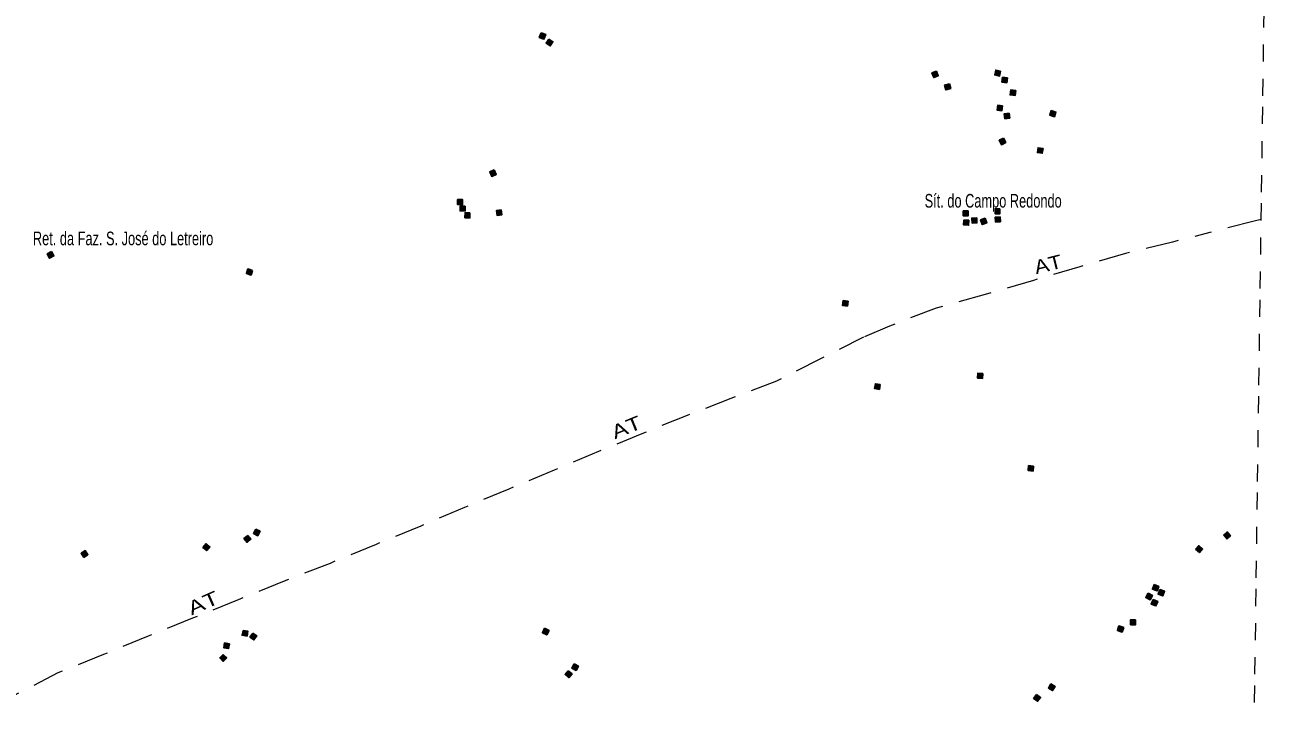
# Model space of a CAD drawing. Extents: x 679 to 705, y 7427.4 to 7455.4.
# Drawn here: x 697.64 to 704.9, y 7443.57 to 7447.55 of the extents above; entities that cross this region are included whole.
import ezdxf
from ezdxf.enums import TextEntityAlignment as Align

# ---------------------------------------------------------------- set-up
doc = ezdxf.new("R2010")
doc.units = 0
doc.header["$LTSCALE"] = 0.032
doc.linetypes.add('DOT_DASHED', pattern=[7.7, 5, -1.2, 0.3, -1.2])
doc.linetypes.add('SHORT_DASHED', pattern=[2.7, 1.5, -1.2])
for name, color, linetype, lineweight in [('2', 7, 'Continuous', 25), ('56', 7, 'DOT_DASHED', 13), ('58', 7, 'SHORT_DASHED', 13)]:
    doc.layers.add(name, color=color, linetype=linetype, lineweight=lineweight)
doc.layers.add('61', color=7, linetype='Continuous')

msp = doc.modelspace()

# ---------------------------------------------------------------- hatches: boundary and pattern name
at = {"layer": '2'}
for points in [[(700.6624, 7447.5073), (700.6893, 7447.4964), (700.6784, 7447.4695), (700.6515, 7447.4804)], [(700.7072, 7447.4701), (700.7317, 7447.4546), (700.7161, 7447.4301), (700.6917, 7447.4456)], [(702.9796, 7447.2825), (702.9902, 7447.2555), (702.9632, 7447.2449), (702.9526, 7447.2719)], [(703.3556, 7447.2814), (703.3489, 7447.2532), (703.3207, 7447.2599), (703.3273, 7447.2881)], [(703.0551, 7447.2082), (703.0629, 7447.1803), (703.035, 7447.1725), (703.0272, 7447.2004)], [(703.3959, 7447.2431), (703.3921, 7447.2144), (703.3633, 7447.2181), (703.3671, 7447.2469)], [(703.4438, 7447.168), (703.4398, 7447.1393), (703.4111, 7447.1433), (703.4151, 7447.172)], [(703.3672, 7447.0788), (703.3634, 7447.05), (703.3346, 7447.0538), (703.3385, 7447.0826)], [(703.4048, 7447.0362), (703.4089, 7447.0075), (703.3802, 7447.0034), (703.3761, 7447.0321)], [(703.6526, 7447.0522), (703.68, 7447.0427), (703.6705, 7447.0153), (703.6431, 7447.0248)], [(703.3723, 7446.8905), (703.3859, 7446.8649), (703.3602, 7446.8513), (703.3467, 7446.877)], [(703.604, 7446.8293), (703.5995, 7446.8007), (703.5709, 7446.8052), (703.5753, 7446.8338)], [(700.3873, 7446.7035), (700.3994, 7446.6772), (700.3731, 7446.6651), (700.361, 7446.6914)], [(700.1727, 7446.5295), (700.2017, 7446.5295), (700.2017, 7446.5005), (700.1727, 7446.5005)], [(700.2179, 7446.4912), (700.2167, 7446.4622), (700.1878, 7446.4634), (700.1889, 7446.4924)], [(700.4288, 7446.4697), (700.4331, 7446.441), (700.4044, 7446.4367), (700.4002, 7446.4654)], [(703.1651, 7446.463), (703.1651, 7446.434), (703.1361, 7446.434), (703.1361, 7446.463)], [(703.3517, 7446.4758), (703.3517, 7446.4468), (703.3227, 7446.4468), (703.3227, 7446.4758)], [(700.2454, 7446.4516), (700.2447, 7446.4226), (700.2158, 7446.4232), (700.2164, 7446.4522)], [(703.1691, 7446.408), (703.1674, 7446.3791), (703.1385, 7446.3807), (703.1401, 7446.4096)], [(703.2153, 7446.4223), (703.2169, 7446.3933), (703.188, 7446.3917), (703.1864, 7446.4207)], [(703.2649, 7446.4205), (703.2746, 7446.3931), (703.2473, 7446.3835), (703.2376, 7446.4108)], [(703.3527, 7446.4285), (703.3539, 7446.3995), (703.3249, 7446.3983), (703.3237, 7446.4273)], [(697.7938, 7446.2253), (697.8075, 7446.1997), (697.782, 7446.186), (697.7683, 7446.2115)], [(698.9716, 7446.1148), (698.9629, 7446.0872), (698.9352, 7446.0959), (698.944, 7446.1236)], [(702.4614, 7445.9341), (702.4574, 7445.9054), (702.4287, 7445.9093), (702.4326, 7445.9381)], [(703.2515, 7445.5106), (703.2493, 7445.4817), (703.2204, 7445.4839), (703.2226, 7445.5128)], [(702.6498, 7445.4455), (702.6451, 7445.4169), (702.6165, 7445.4216), (702.6212, 7445.4502)], [(703.5486, 7444.9677), (703.5458, 7444.9388), (703.517, 7444.9416), (703.5198, 7444.9705)], [(698.9895, 7444.5986), (699.0153, 7444.5853), (699.0021, 7444.5595), (698.9763, 7444.5728)], [(704.6618, 7444.5626), (704.6837, 7444.5815), (704.7027, 7444.5596), (704.6807, 7444.5406)], [(698.6984, 7444.5133), (698.721, 7444.4951), (698.7028, 7444.4725), (698.6802, 7444.4907)], [(698.9428, 7444.5613), (698.9616, 7444.5392), (698.9395, 7444.5204), (698.9207, 7444.5424)], [(704.4985, 7444.4799), (704.5175, 7444.5017), (704.5394, 7444.4827), (704.5203, 7444.4608)], [(697.9815, 7444.4321), (697.9658, 7444.4565), (697.9902, 7444.4722), (698.0059, 7444.4478)], [(704.2194, 7444.223), (704.245, 7444.2093), (704.2313, 7444.1837), (704.2057, 7444.1974)], [(704.2553, 7444.2731), (704.2825, 7444.2629), (704.2722, 7444.2357), (704.2451, 7444.246)], [(704.289, 7444.2445), (704.316, 7444.2339), (704.3055, 7444.2069), (704.2785, 7444.2175)], [(704.2491, 7444.1854), (704.2761, 7444.175), (704.2657, 7444.1479), (704.2386, 7444.1584)], [(704.1463, 7444.0669), (704.1463, 7444.0379), (704.1173, 7444.0379), (704.1173, 7444.0669)], [(698.9157, 7444.005), (698.9441, 7443.9996), (698.9387, 7443.9711), (698.9102, 7443.9765)], [(698.9726, 7443.989), (698.9963, 7443.9723), (698.9796, 7443.9486), (698.9559, 7443.9653)], [(700.683, 7444.0171), (700.7089, 7444.0039), (700.6957, 7443.978), (700.6699, 7443.9912)], [(704.0767, 7444.022), (704.0675, 7443.9945), (704.04, 7444.0036), (704.0491, 7444.0312)], [(698.836, 7443.9261), (698.8304, 7443.8977), (698.8019, 7443.9034), (698.8076, 7443.9318)], [(698.7988, 7443.8643), (698.8196, 7443.844), (698.7993, 7443.8233), (698.7786, 7443.8436)], [(700.8216, 7443.7685), (700.8435, 7443.7495), (700.8244, 7443.7276), (700.8026, 7443.7467)], [(700.8554, 7443.8091), (700.8811, 7443.7957), (700.8677, 7443.77), (700.842, 7443.7834)], [(703.566, 7443.6297), (703.5892, 7443.6123), (703.5718, 7443.5891), (703.5486, 7443.6065)], [(703.6507, 7443.6916), (703.6751, 7443.6761), (703.6596, 7443.6516), (703.6351, 7443.6671)]]:
    msp.add_hatch(color=256, dxfattribs=at).paths.add_polyline_path(points)

# ---------------------------------------------------------------- linework, layer by layer
for points in [[(700.6624, 7447.5073), (700.6893, 7447.4964), (700.6784, 7447.4695), (700.6515, 7447.4804)], [(700.7072, 7447.4701), (700.7317, 7447.4546), (700.7161, 7447.4301), (700.6917, 7447.4456)], [(702.9796, 7447.2825), (702.9902, 7447.2555), (702.9632, 7447.2449), (702.9526, 7447.2719)], [(703.3556, 7447.2814), (703.3489, 7447.2532), (703.3207, 7447.2599), (703.3273, 7447.2881)], [(703.0551, 7447.2082), (703.0629, 7447.1803), (703.035, 7447.1725), (703.0272, 7447.2004)], [(703.3959, 7447.2431), (703.3921, 7447.2144), (703.3633, 7447.2181), (703.3671, 7447.2469)], [(703.4438, 7447.168), (703.4398, 7447.1393), (703.4111, 7447.1433), (703.4151, 7447.172)], [(703.3672, 7447.0788), (703.3634, 7447.05), (703.3346, 7447.0538), (703.3385, 7447.0826)], [(703.4048, 7447.0362), (703.4089, 7447.0075), (703.3802, 7447.0034), (703.3761, 7447.0321)], [(703.6526, 7447.0522), (703.68, 7447.0427), (703.6705, 7447.0153), (703.6431, 7447.0248)], [(703.3723, 7446.8905), (703.3859, 7446.8649), (703.3602, 7446.8513), (703.3467, 7446.877)], [(703.604, 7446.8293), (703.5995, 7446.8007), (703.5709, 7446.8052), (703.5753, 7446.8338)], [(700.3873, 7446.7035), (700.3994, 7446.6772), (700.3731, 7446.6651), (700.361, 7446.6914)], [(700.1727, 7446.5295), (700.2017, 7446.5295), (700.2017, 7446.5005), (700.1727, 7446.5005)], [(700.2179, 7446.4912), (700.2167, 7446.4622), (700.1878, 7446.4634), (700.1889, 7446.4924)], [(700.4288, 7446.4697), (700.4331, 7446.441), (700.4044, 7446.4367), (700.4002, 7446.4654)], [(703.1651, 7446.463), (703.1651, 7446.434), (703.1361, 7446.434), (703.1361, 7446.463)], [(703.3517, 7446.4758), (703.3517, 7446.4468), (703.3227, 7446.4468), (703.3227, 7446.4758)], [(700.2454, 7446.4516), (700.2447, 7446.4226), (700.2158, 7446.4232), (700.2164, 7446.4522)], [(703.1691, 7446.408), (703.1674, 7446.3791), (703.1385, 7446.3807), (703.1401, 7446.4096)], [(703.2153, 7446.4223), (703.2169, 7446.3933), (703.188, 7446.3917), (703.1864, 7446.4207)], [(703.2649, 7446.4205), (703.2746, 7446.3931), (703.2473, 7446.3835), (703.2376, 7446.4108)], [(703.3527, 7446.4285), (703.3539, 7446.3995), (703.3249, 7446.3983), (703.3237, 7446.4273)], [(697.7938, 7446.2253), (697.8075, 7446.1997), (697.782, 7446.186), (697.7683, 7446.2115)], [(698.9716, 7446.1148), (698.9629, 7446.0872), (698.9352, 7446.0959), (698.944, 7446.1236)], [(702.4614, 7445.9341), (702.4574, 7445.9054), (702.4287, 7445.9093), (702.4326, 7445.9381)], [(703.2515, 7445.5106), (703.2493, 7445.4817), (703.2204, 7445.4839), (703.2226, 7445.5128)], [(702.6498, 7445.4455), (702.6451, 7445.4169), (702.6165, 7445.4216), (702.6212, 7445.4502)], [(703.5486, 7444.9677), (703.5458, 7444.9388), (703.517, 7444.9416), (703.5198, 7444.9705)], [(698.9895, 7444.5986), (699.0153, 7444.5853), (699.0021, 7444.5595), (698.9763, 7444.5728)], [(704.6618, 7444.5626), (704.6837, 7444.5815), (704.7027, 7444.5596), (704.6807, 7444.5406)], [(698.6984, 7444.5133), (698.721, 7444.4951), (698.7028, 7444.4725), (698.6802, 7444.4907)], [(698.9428, 7444.5613), (698.9616, 7444.5392), (698.9395, 7444.5204), (698.9207, 7444.5424)], [(704.4985, 7444.4799), (704.5175, 7444.5017), (704.5394, 7444.4827), (704.5203, 7444.4608)], [(697.9815, 7444.4321), (697.9658, 7444.4565), (697.9902, 7444.4722), (698.0059, 7444.4478)], [(704.2194, 7444.223), (704.245, 7444.2093), (704.2313, 7444.1837), (704.2057, 7444.1974)], [(704.2553, 7444.2731), (704.2825, 7444.2629), (704.2722, 7444.2357), (704.2451, 7444.246)], [(704.289, 7444.2445), (704.316, 7444.2339), (704.3055, 7444.2069), (704.2785, 7444.2175)], [(704.2491, 7444.1854), (704.2761, 7444.175), (704.2657, 7444.1479), (704.2386, 7444.1584)], [(704.1463, 7444.0669), (704.1463, 7444.0379), (704.1173, 7444.0379), (704.1173, 7444.0669)], [(698.9157, 7444.005), (698.9441, 7443.9996), (698.9387, 7443.9711), (698.9102, 7443.9765)], [(698.9726, 7443.989), (698.9963, 7443.9723), (698.9796, 7443.9486), (698.9559, 7443.9653)], [(700.683, 7444.0171), (700.7089, 7444.0039), (700.6957, 7443.978), (700.6699, 7443.9912)], [(704.0767, 7444.022), (704.0675, 7443.9945), (704.04, 7444.0036), (704.0491, 7444.0312)], [(698.836, 7443.9261), (698.8304, 7443.8977), (698.8019, 7443.9034), (698.8076, 7443.9318)], [(698.7988, 7443.8643), (698.8196, 7443.844), (698.7993, 7443.8233), (698.7786, 7443.8436)], [(700.8216, 7443.7685), (700.8435, 7443.7495), (700.8244, 7443.7276), (700.8026, 7443.7467)], [(700.8554, 7443.8091), (700.8811, 7443.7957), (700.8677, 7443.77), (700.842, 7443.7834)], [(703.566, 7443.6297), (703.5892, 7443.6123), (703.5718, 7443.5891), (703.5486, 7443.6065)], [(703.6507, 7443.6916), (703.6751, 7443.6761), (703.6596, 7443.6516), (703.6351, 7443.6671)]]:
    msp.add_lwpolyline(points, close=True, dxfattribs=at)
at = {"layer": '56'}
msp.add_lwpolyline([(704.8826, 7446.4125), (704.842, 7446.4026), (704.3631, 7446.2806), (704.0865, 7446.213), (703.8189, 7446.1362), (703.5478, 7446.0563), (703.2649, 7445.9728), (702.9772, 7445.8937), (702.705, 7445.7877), (702.5519, 7445.7236), (702.3007, 7445.596), (702.0427, 7445.4652), (701.7746, 7445.3645), (701.5192, 7445.2643), (701.2535, 7445.1576), (700.9979, 7445.0524), (700.7385, 7444.9435), (700.4723, 7444.8331), (700.2126, 7444.7249), (699.9565, 7444.6163), (699.6947, 7444.5089), (699.4252, 7444.3977), (699.1556, 7444.2932), (698.8869, 7444.1836), (698.6196, 7444.0758), (698.3592, 7443.9713), (698.0971, 7443.8628), (697.8309, 7443.7554), (697.5731, 7443.6239)], dxfattribs=at)
at = {"layer": '58'}
msp.add_lwpolyline([(704.7919, 7439.7922), (704.7996, 7440.3572), (704.8074, 7440.9223), (704.8151, 7441.4873), (704.8229, 7442.0524), (704.8306, 7442.6174), (704.8384, 7443.1825), (704.8461, 7443.7476), (704.8539, 7444.3126), (704.8616, 7444.8777), (704.8693, 7445.4427), (704.8771, 7446.0078), (704.8848, 7446.5728), (704.8925, 7447.1379), (704.9003, 7447.7029)], dxfattribs=at)

# ---------------------------------------------------------------- texts
at = {"layer": '61', "width": 0.7}
for s, p in [('Sít. do Campo Redondo', (702.9101, 7446.4826)), ('Ret. da Faz. S. José do Letreiro', (697.6838, 7446.2619))]:
    msp.add_text(s, height=0.08, dxfattribs=at).set_placement(p)
at = {"layer": '61'}
for rotation, width, p in [(14.045, 1.2, (703.643, 7446.1117)), (22.309, 1.3, (701.1771, 7445.1583)), (23.954, 1.35, (698.6978, 7444.129))]:
    msp.add_text('AT', height=0.08, rotation=rotation, dxfattribs=dict(at, width=width)).set_placement(p, align=Align.CENTER)

doc.saveas('drawing.dxf')
